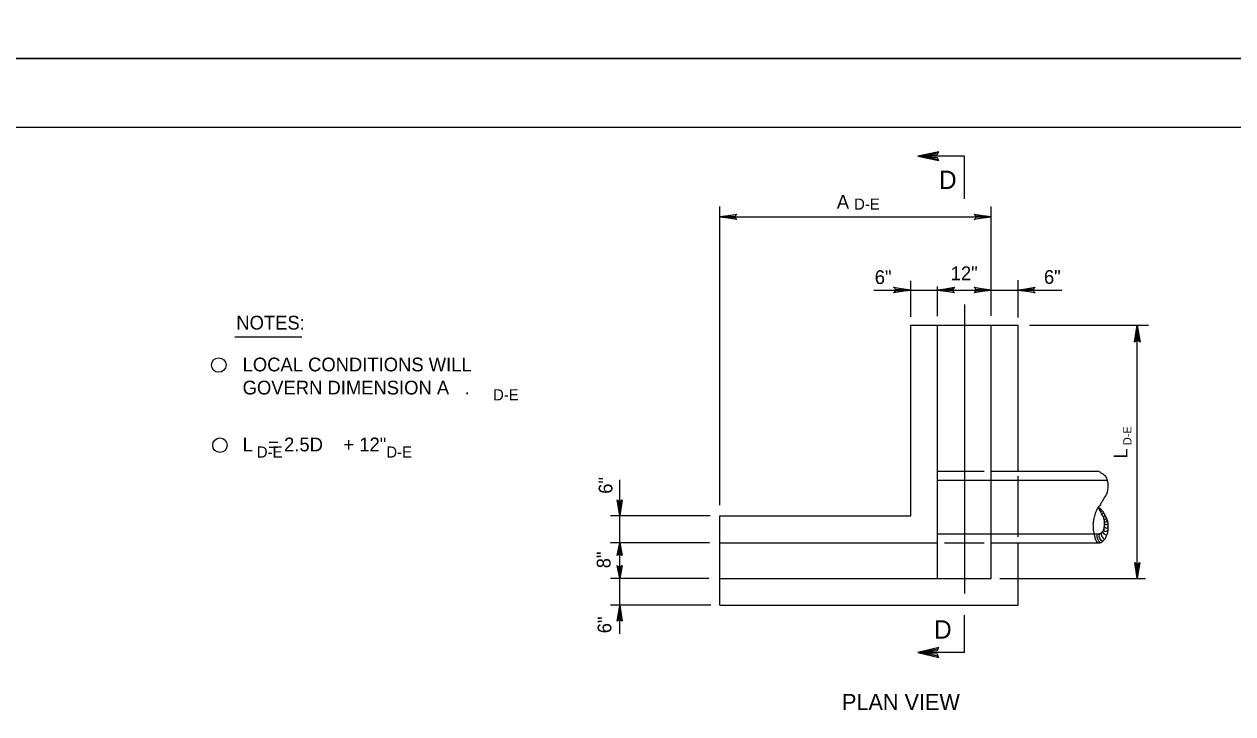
# Model space of a CAD drawing. Extents: x 638877 to 639960, y 297341 to 299123.
# Drawn here: x 639193.8 to 639457.3, y 298386.4 to 298536.8 of the extents above; entities that cross this region are included whole.
import ezdxf

# ---------------------------------------------------------------- set-up
doc = ezdxf.new("R2010")
doc.units = 0
for name, color, linetype in [('1', 7, 'Continuous'), ('2', 7, 'Continuous'), ('3', 7, 'Continuous'), ('PLT-BNDY', 7, 'Continuous')]:
    doc.layers.add(name, color=color, linetype=linetype)

msp = doc.modelspace()

# ---------------------------------------------------------------- linework, layer by layer
at = {"layer": '1'}
for p, q in [((639703.19, 298514.28), (638917.19, 298514.28)), ((639398.74, 298498.68), (639398.74, 298507.99)), ((639398.74, 298475.64), (639398.74, 298412.62)), ((639398.74, 298399.73), (639398.74, 298407.86))]:
    msp.add_line(p, q, dxfattribs=at)
for centre in [(639236.2, 298462.44), (639236.45, 298444.95)]:
    msp.add_circle(centre, 1.58, dxfattribs=at)
at = {"layer": '2'}
for p, q in [((639398.74, 298507.99), (639388.6, 298507.99)), ((639345.44, 298431.85), (639345.44, 298496.98)), ((639404.59, 298473.15), (639404.59, 298496.98)), ((639345.44, 298494.76), (639404.59, 298494.76)), ((639379, 298478.8), (639392.89, 298478.8)), ((639387.04, 298472.96), (639387.04, 298480.79)), ((639392.89, 298473.1), (639392.89, 298479.57)), ((639392.89, 298478.8), (639404.59, 298478.8)), ((639404.59, 298478.8), (639420.02, 298478.8)), ((639410.44, 298472.81), (639410.44, 298480.94)), ((639387.04, 298429.54), (639387.04, 298471.14)), ((639387.04, 298471.14), (639410.44, 298471.14)), ((639392.89, 298415.89), (639392.89, 298471.14)), ((639404.59, 298415.89), (639404.59, 298471.14)), ((639410.44, 298439.29), (639410.44, 298471.14)), ((639412.92, 298471.14), (639438.91, 298471.14)), ((639436.44, 298415.89), (639436.44, 298471.14)), ((639254.33, 298468.52), (639239.67, 298468.52)), ((639392.89, 298439.29), (639403.06, 298439.29)), ((639404.59, 298439.29), (639427.99, 298439.29)), ((639323.6, 298423.69), (639323.6, 298437.42)), ((639392.89, 298437.34), (639429.74, 298437.34)), ((639410.44, 298424.96), (639410.44, 298438.2)), ((639323.6, 298429.54), (639323.6, 298435.42)), ((639343.3, 298429.54), (639321.63, 298429.54)), ((639345.44, 298429.54), (639387.04, 298429.54)), ((639345.44, 298410.04), (639345.44, 298429.54)), ((639392.89, 298425.64), (639426.97, 298425.64)), ((639343.18, 298423.69), (639321.63, 298423.69)), ((639323.6, 298415.89), (639323.6, 298423.69)), ((639345.44, 298423.69), (639392.89, 298423.69)), ((639394.44, 298423.69), (639403.06, 298423.69)), ((639404.59, 298423.69), (639427.99, 298423.69)), ((639410.44, 298410.04), (639410.44, 298423.69)), ((639343.03, 298415.89), (639321.63, 298415.89)), ((639323.6, 298403.78), (639323.6, 298415.89)), ((639345.44, 298415.89), (639404.59, 298415.89)), ((639406.49, 298415.89), (639438.24, 298415.89)), ((639343.44, 298410.04), (639321.63, 298410.04)), ((639345.44, 298410.04), (639410.44, 298410.04)), ((639398.74, 298399.73), (639388.6, 298399.73))]:
    msp.add_line(p, q, dxfattribs=at)
for points in [[(639392.96, 298508.72), (639392.8, 298508.3), (639388.6, 298507.99), (639392.96, 298508.72), (639393.19, 298508.97), (639388.6, 298507.99), (639392.8, 298507.71), (639392.95, 298507.3), (639388.6, 298507.99), (639393.19, 298507.02), (639392.95, 298507.3)], [(639348.98, 298494.32), (639348.85, 298494.57), (639345.44, 298494.76), (639348.98, 298494.32), (639349.17, 298494.16), (639345.44, 298494.76), (639348.85, 298494.93), (639348.97, 298495.18), (639345.44, 298494.76), (639349.17, 298495.35), (639348.97, 298495.18)], [(639401.05, 298495.21), (639401.19, 298494.95), (639404.59, 298494.76), (639401.05, 298495.21), (639400.87, 298495.36), (639404.59, 298494.76), (639401.19, 298494.59), (639401.06, 298494.34), (639404.59, 298494.76), (639400.87, 298494.17), (639401.06, 298494.34)], [(639383.5, 298479.25), (639383.64, 298478.99), (639387.04, 298478.8), (639383.5, 298479.25), (639383.32, 298479.4), (639387.04, 298478.8), (639383.64, 298478.63), (639383.51, 298478.38), (639387.04, 298478.8), (639383.32, 298478.21), (639383.51, 298478.38)], [(639396.43, 298478.36), (639396.3, 298478.62), (639392.89, 298478.8), (639396.43, 298478.36), (639396.62, 298478.2), (639392.89, 298478.8), (639396.3, 298478.97), (639396.42, 298479.22), (639392.89, 298478.8), (639396.62, 298479.4), (639396.42, 298479.22)], [(639401.05, 298479.25), (639401.19, 298478.99), (639404.59, 298478.8), (639401.05, 298479.25), (639400.87, 298479.4), (639404.59, 298478.8), (639401.19, 298478.63), (639401.06, 298478.38), (639404.59, 298478.8), (639400.87, 298478.21), (639401.06, 298478.38)], [(639413.98, 298478.36), (639413.85, 298478.62), (639410.44, 298478.8), (639413.98, 298478.36), (639414.17, 298478.2), (639410.44, 298478.8), (639413.85, 298478.97), (639413.97, 298479.22), (639410.44, 298478.8), (639414.17, 298479.4), (639413.97, 298479.22)], [(639436, 298467.6), (639436.26, 298467.74), (639436.44, 298471.14), (639436, 298467.6), (639435.84, 298467.42), (639436.44, 298471.14), (639436.61, 298467.74), (639436.86, 298467.61), (639436.44, 298471.14), (639437.04, 298467.42), (639436.86, 298467.61)], [(639324.02, 298432.85), (639323.78, 298432.73), (639323.6, 298429.54), (639324.02, 298432.85), (639324.16, 298433.02), (639323.6, 298429.54), (639323.45, 298432.72), (639323.21, 298432.84), (639323.6, 298429.54), (639323.05, 298433.02), (639323.21, 298432.84)], [(639323.19, 298421.04), (639323.42, 298421.14), (639323.6, 298423.68), (639323.19, 298421.04), (639323.04, 298420.9), (639323.6, 298423.68), (639323.76, 298421.14), (639324, 298421.05), (639323.6, 298423.68), (639324.15, 298420.9), (639324, 298421.05)], [(639324.02, 298418.56), (639323.78, 298418.46), (639323.6, 298415.92), (639324.02, 298418.56), (639324.16, 298418.7), (639323.6, 298415.92), (639323.45, 298418.46), (639323.21, 298418.56), (639323.6, 298415.92), (639323.05, 298418.7), (639323.21, 298418.56)], [(639436.86, 298419.2), (639436.62, 298419.08), (639436.44, 298415.89), (639436.86, 298419.2), (639437, 298419.37), (639436.44, 298415.89), (639436.29, 298419.07), (639436.05, 298419.19), (639436.44, 298415.89), (639435.89, 298419.37), (639436.05, 298419.19)], [(639323.19, 298406.74), (639323.42, 298406.86), (639323.6, 298410.04), (639323.19, 298406.74), (639323.04, 298406.57), (639323.6, 298410.04), (639323.76, 298406.86), (639324, 298406.75), (639323.6, 298410.04), (639324.15, 298406.57), (639324, 298406.75)], [(639392.96, 298400.54), (639392.8, 298400.08), (639388.6, 298399.73), (639392.96, 298400.54), (639393.19, 298400.81), (639388.6, 298399.73), (639392.8, 298399.43), (639392.95, 298398.98), (639388.6, 298399.73), (639393.19, 298398.67), (639392.95, 298398.98)]]:
    msp.add_lwpolyline(points, dxfattribs=at)
for centre, radius, start, end in [((639428.36, 298430.89), 0.127, 176.947, 93.053), ((639428.46, 298430.76), 0.298, 285.6074, 325.806), ((639428.85, 298430.14), 0.173, 195.7562, 33.8551), ((639429.18, 298429.61), 0.174, 203.3341, 43.8053), ((639429.44, 298429.03), 0.253, 188.5456, 52.8367), ((639429.52, 298428.53), 0.291, 223.7085, 2.3299), ((639429.76, 298425.54), 1.18, 164.8508, 242.5231), ((639429.61, 298426.08), 0.667, 173.2089, 278.5784), ((639429.57, 298426.57), 0.415, 171.0795, 335.4873), ((639429.69, 298427.23), 0.359, 199.7004, 348.5016), ((639429.65, 298427.95), 0.315, 212.411, 346.6825), ((639429.27, 298425.18), 1.67, 168.491, 237.5129), ((639429.26, 298425.16), 1.18, 158.8965, 245.9336)]:
    msp.add_arc(centre, radius, start, end, dxfattribs=at)
for points in [[(639427.99, 298439.29), (639428.5, 298438.95), (639429.02, 298438.62), (639429.59, 298437.97), (639429.95, 298437.02), (639429.97, 298435.23), (639429.69, 298434.26), (639429.24, 298433.54), (639428.83, 298432.78), (639428.52, 298432.26), (639428.26, 298431.8), (639427.99, 298431.49), (639427.59, 298430.9), (639427.35, 298430.28), (639427.04, 298429.26), (639426.9, 298428.64), (639426.78, 298427.9), (639426.78, 298427.35), (639426.85, 298426.42), (639427.04, 298425.44), (639427.21, 298424.73), (639427.57, 298423.99), (639427.99, 298423.69), (639428.54, 298423.73), (639429.07, 298424.18), (639429.5, 298424.71), (639429.79, 298425.32), (639430.02, 298426.14), (639430.09, 298427.11), (639430.07, 298427.92), (639429.81, 298428.92), (639429.43, 298429.66), (639429.07, 298430.33), (639428.62, 298430.85), (639427.99, 298431.49)], [(639426.97, 298425.64), (639427.45, 298425.61), (639428.07, 298425.66), (639428.4, 298425.71), (639428.66, 298425.95), (639428.85, 298426.14), (639429.05, 298426.44), (639429.19, 298426.87), (639429.28, 298427.33), (639429.31, 298427.83), (639429.31, 298428.25), (639429.21, 298428.71), (639429.12, 298429.14), (639428.95, 298429.44), (639428.64, 298429.99), (639428.54, 298430.26), (639428.45, 298430.49), (639428.19, 298430.9), (639428.07, 298431.18), (639427.99, 298431.49)]]:
    msp.add_spline(points, degree=3, dxfattribs=at)
at = {"layer": 'PLT-BNDY'}
for points in [[(638877.19, 299123.28), (639718.19, 299123.28), (639718.19, 298529.28), (638877.19, 298529.28)], [(638877.19, 298529.28), (639718.19, 298529.28), (639718.19, 297935.28), (638877.19, 297935.28)]]:
    msp.add_lwpolyline(points, close=True, dxfattribs=at)

# ---------------------------------------------------------------- texts
at = {"layer": '1'}
for s, height, p in [('D-E', 2.43, (639374.7, 298496.32)), ('NOTES:', 3, (639240.02, 298470.18)), ('LOCAL CONDITIONS WILL', 3, (639241.4, 298461.06)), ('GOVERN DIMENSION A   .', 3, (639241.4, 298456.02)), ('D-E', 2.43, (639296, 298454.73)), ('L   = 2.5D    + 12"', 3, (639241.4, 298443.61)), ('D-E', 2.43, (639244.5, 298442.25)), ('D-E', 2.43, (639272.72, 298442.25))]:
    msp.add_text(s, height=height, dxfattribs=at).set_placement(p)
msp.add_text('D-E', height=1.8, rotation=90, dxfattribs=at).set_placement((639435.17, 298444.95))
at = {"layer": '2'}
msp.add_text('L', height=3, rotation=90, dxfattribs=at).set_placement((639434.29, 298442.05))
at = {"layer": '3'}
for s, height, p in [('D', 3.99, (639393.19, 298500.84)), ('A', 3, (639370.93, 298496.53)), ('12"', 3, (639395.76, 298480.94)), ('6"', 3, (639379.2, 298480.11)), ('6"', 3, (639416.09, 298480.14)), ('D', 3.99, (639392.12, 298402.77)), ('PLAN VIEW', 3.53, (639372.06, 298387.19))]:
    msp.add_text(s, height=height, dxfattribs=at).set_placement(p)
for s, p in [('6"', (639322.01, 298434.36)), ('8"', (639321.6, 298418.11)), ('6"', (639321.78, 298403.94))]:
    msp.add_text(s, height=3, rotation=90, dxfattribs=at).set_placement(p)

doc.saveas('drawing.dxf')
